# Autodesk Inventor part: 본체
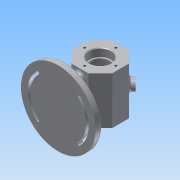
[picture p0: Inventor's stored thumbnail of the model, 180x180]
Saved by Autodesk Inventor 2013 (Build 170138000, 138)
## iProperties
Created: 2017-06
Part Number: 본체
Material: 알루미늄 6061
Document SubType Name: Modeling
Designer: Administrator
Density: 2.71 g/cm^3
Mass: 564.042 g
Surface Area: 566.824 cm^2
Volume: 208.134 cm^3
Author: Administrator
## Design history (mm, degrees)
sketch "스케치2" dims "d0" = 60
  geometry: L1 (12.426, 30)-(30, 12.426); L2 (30, 12.426)-(30, -12.426); L3 (30, -12.426)-(12.426, -30); L4 (12.426, -30)-(-12.426, -30); L5 (-12.426, -30)-(-30, -12.426); L6 (-30, -12.426)-(-30, 12.426); L7 (-30, 12.426)-(-12.426, 30); L8 (-12.426, 30)-(12.426, 30); L9 (0, 0)-(12.426, 30); L10 (0, 30)-(0, 0); 3 further points
  constraints: 20 end point, 3 coincident, 1 midpoint, 1 perpendicular, 1 vertical alignment, 19 other
extrude "돌출1" new body sketch "스케치2" stored distance "d2" = 70; taper "d3" = 0 deg
sketch "스케치3"
  geometry: L1 (30, -35)-(-30, -35) reference; L2 (-30, -35)-(-30, 35) reference; L3 (-30, 35)-(30, 35) reference; L4 (30, 35)-(30, -35) reference; L5 (16, 35)-(16, 23.3); L6 (15.7, 23)-(14, 23); L7 (14, 23)-(14, 20); L8 (14, 20)-(22, 20); L9 (25, 17)-(25, -17) reference; L10 (22, -20)-(14, -20); L11 (14, -20)-(14, -23); L12 (14, -23)-(15.7, -23); L13 (16, -23.3)-(16, -35); L14 (0, 44.777)-(0, -45.565); L15 (16, 35)-(0, 35); L16 (16, -35)-(0, -35); L17 (16, -35)-(0, -35); A1 r 3 centre (22, -17) between (22, -20) and (25, -17); A2 r 3 centre (22, 17) between (25, 17) and (22, 20); A3 r 0.3 centre (15.7, 23.3) between (15.7, 23) and (16, 23.3); A4 r 0.3 centre (15.7, -23.3) between (16, -23.3) and (15.7, -23); 4 further points
  constraints: 26 end point, 8 point on circle, 8 point on line, 8 tangent, 6 parallel, 4 centre point, 3 midpoint, 2 collinear, 2 equal radius, 2 perpendicular, 2 vertical
  dimensions: "d5" = 32 diameter of L5 L14; "d7" = 28 diameter of L7 L14; "d8" = 50 diameter of L9 L14; "d9" = 40 distance between parallel lines of L10 L8; "d10" = 28 diameter of L11 L14; "d11" = 32 diameter of L13 L14; "d12" = 12 distance of L5.start point (16, 23); "d13" = 12 distance of point (16, -23) L13.end; "d14" = 3 radius of A1; "d16" = 0.3 radius of A3
revolve "회전1" sketch "스케치3" stored, may be unused: angle "d15" = 90 deg
node "작업 평면1"
sketch "스케치4"
  geometry: L1 (0, 0)-(69.994, 0); L2 (0, 0)-(-72.326, 0); C1 r 55 at (0, 0); A1 r 48 centre (0, 0) between (-33.941, 33.941) and (-33.941, -33.941); A2 r 48 centre (0, 0) between (33.941, -33.941) and (33.941, 33.941); A3 r 38 centre (0, 0) between (26.87, -26.87) and (26.87, 26.87); A4 r 38 centre (0, 0) between (-26.87, 26.87) and (-26.87, -26.87); A5 r 5 centre (-30.406, 30.406) between (-26.87, 26.87) and (-33.941, 33.941); A6 r 5 centre (-30.406, -30.406) between (-33.941, -33.941) and (-26.87, -26.87); A7 r 5 centre (30.406, 30.406) between (33.941, 33.941) and (26.87, 26.87); A8 r 5 centre (30.406, -30.406) between (26.87, -26.87) and (33.941, -33.941); A9 r 45 centre (0, 0) between (31.82, -31.82) and (31.82, 31.82); A10 r 2 centre (30.406, -30.406) between (28.991, -28.991) and (31.82, -31.82); A11 r 41 centre (0, 0) between (28.991, -28.991) and (28.991, 28.991); A12 r 2 centre (30.406, 30.406) between (31.82, 31.82) and (28.991, 28.991); A13 r 41 centre (0, 0) between (-28.991, 28.991) and (-28.991, -28.991); A14 r 2 centre (-30.406, 30.406) between (-28.991, 28.991) and (-31.82, 31.82); A15 r 45 centre (0, 0) between (-31.82, 31.82) and (-31.82, -31.82); A16 r 2 centre (-30.406, -30.406) between (-31.82, -31.82) and (-28.991, -28.991); 1 further point
  constraints: 32 point on circle, 17 centre point, 4 end point, 4 tangent, 3 coincident, 1 collinear, 1 horizontal, 6 other
  dimensions: "d18" = 110 diameter of C1; "d26" = 5 radius of A8; "d27" = 5 radius of A6; "d28" = 48 radius of A2; "d29" = 48 radius of A1; "d30" = 38 radius of A4; "d31" = 38 radius of A3; "d32" = 5 radius of A7; "d33" = 5 radius of A5; "d35" = 30.40559 distance from line of L1 A7.centre; "d39" = 30.40559 distance from line of L1 A8.centre; "d40" = 30.40559 distance from line of L2 A6.centre; "d41" = 30.40559 distance from line of L2 A5.centre; "d42" = 3 radial gap between concentric circles of A2 A9; "d43" = 3 radial gap between concentric circles of A4 A13
extrude "돌출2" join sketch "스케치4" distance "d44" = 10; taper "d45" = 0 deg
extrude "돌출4" join sketch "스케치4" distance "d48" = 7; taper "d49" = 0 deg
sketch "스케치5"
  geometry: L1 (5, -24)-(-5, -24); L2 (-5, -24)-(-5, 24); L3 (-5, 24)-(5, 24); L4 (5, 24)-(5, -24); L5 (5, -24)-(-5, 24); L6 (-5, -24)-(5, 24); A1 r 5 centre (0, -24) between (-5, -24) and (5, -24); A2 r 5 centre (0, 24) between (5, 24) and (-5, 24); 1 further point
  constraints: 12 end point, 4 midpoint, 4 point on circle, 2 centre point, 2 parallel, 1 horizontal, 1 perpendicular
  dimensions: "d50" = 48 distance of L2.end L1.end; "d52" = 10 distance of L2.end L3.end
extrude "돌출5" join sketch "스케치5" stored distance "d53" = 7; taper "d54" = 0 deg
sketch "스케치6"
  geometry: C1 r 8 at (-12.426, 35); C2 r 4 at (-12.426, 35); 1 further point
  constraints: 2 centre point, 2 coincident
  dimensions: "d55" = 16 diameter of C1; "d57" = 8 diameter of C2
extrude "돌출6" join sketch "스케치6" distance "d58" = 7; taper "d59" = 0 deg
extrude "돌출7" cut sketch "스케치6" distance "d60" = 20; taper "d61" = 0 deg
fillet "모깎기1" dims "d62" = 1, "d63" = 5, "d64" = 3
chamfer "모따기1" distance "d65" = 1; stored, may be unused: second distance "d66" = 2, angle "d67" = 45 deg
sketch "스케치7"
  geometry: L1 (-17.695, 0)-(-17.695, 70) reference; L2 (24.024, 0)-(0, 0) reference; 2 further points
  constraints: 1 other
  dimensions: "d68" = 30 distance from line of L1 point (12.305, 35); "d69" = 35 distance from line of L2 point (12.305, 35)
feature "엠보싱1" sketch "스케치7" dims "d0" = 60, "d5" = 32, "d7" = 28, "d8" = 50, "d9" = 40, "d10" = 28, "d11" = 32, "d12" = 12, "d13" = 12, "d14" = 3, "d16" = 0.3, "d70" = 0.5, "d71" = 0
sketch "스케치8"
  geometry: C1 r 3.058 at (0, 23); C2 r 3.198 at (23, 0); C3 r 6.035 at (0, -23); C4 r 5.01 at (-23, 0); A1 r 23 centre (0, 0) between (0, 23) and (23, 0); 1 further point
  constraints: 5 centre point, 4 point on circle, 1 coincident
  dimensions: "d72" = 46 diameter of A1
hole "구멍1" sketch "스케치8" at (23, 0), (0, -23), (-23, 0), (0, 23) diameter "d73" = 3.242; stored, may be unused: countersink angle "d77" = 90 deg, drill point angle "d79" = 118 deg; dims "d74" = 8, "d75" = 4, "d76" = 2, "d78" = 10
sketch "스케치9"
  geometry: C1 r 2.28 at (0, 23); C2 r 4.459 at (23, 0); C3 r 3.895 at (0, -23); C4 r 4.752 at (-23, 0); A1 r 23 centre (0, 0) between (0, 23) and (23, 0); 1 further point
  constraints: 5 centre point, 4 point on circle, 1 coincident
  dimensions: "d80" = 46 diameter of A1
hole "구멍2" sketch "스케치9" at (0, 23), (-23, 0), (0, -23), (23, 0) diameter "d81" = 3.242; stored, may be unused: countersink angle "d85" = 90 deg, drill point angle "d87" = 118 deg; dims "d82" = 8, "d83" = 4, "d84" = 2, "d86" = 10
node "솔리드1"
node "절단 모서리 투영1"
other parameters: "d17" = -62, "d20" = 45 deg, "d22" = 45 deg, "d24" = 76, "d25" = 96
